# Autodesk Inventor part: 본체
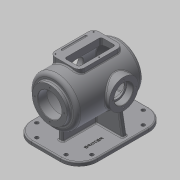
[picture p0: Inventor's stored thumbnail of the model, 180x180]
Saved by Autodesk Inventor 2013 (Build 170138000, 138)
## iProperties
Created: 2016-02
Part Number: 본체
Material: 일반
Document SubType Name: Modeling
Designer: mduedu
Density: 2.71 g/cm^3
Author: mduedu
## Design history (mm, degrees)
sketch "스케치2"
  geometry: L1 (0, 100)-(0, -100); L2 (65, -75.993)-(65, 100); L3 (65, 100)-(0, 100); A1 r 100 centre (0, 0) between (0, -100) and (65, -75.993); 2 further points
  constraints: 6 end point, 2 midpoint, 2 point on circle, 1 centre point, 1 coincident, 1 horizontal, 1 parallel, 1 vertical
  dimensions: "d3" = 200 distance of L1.start L1.end; "d5" = 130 diameter of L2 L1; "d6" = 100 radius of A1
revolve "회전1" sketch "스케치2" stored, may be unused: angle "d7" = 90 deg
sketch "스케치3"
  geometry: C1 r 47.5 at (0, 0); 1 further point
  constraints: 1 centre point, 1 coincident
  dimensions: "d8" = 95 diameter of C1
extrude "돌출2" join sketch "스케치3" distance "d10" = 10; taper "d11" = 0 deg
sketch "스케치5"
  geometry: L1 (47.5, 110)-(47.5, 100) reference; L2 (47.5, 100)-(65, 100) reference; L3 (65, 100)-(65, -75.993) reference; L4 (-65, -75.993)-(-65, 100) reference; L5 (-65, 100)-(-47.5, 100) reference; L6 (-47.5, 100)-(-47.5, 110) reference; L7 (-47.5, 110)-(47.5, 110) reference; L8 (55, 85)-(55, -71.239); L9 (0, 85)-(55, 85); L10 (0, 85)-(0, -90); A1 r 100 centre (0, 0) between (0, -100) and (65, -75.993) reference; A2 r 100 centre (0, 0) between (-65, -75.993) and (0, -100) reference; A3 r 90 centre (0, 0) between (0, -90) and (55, -71.239); 1 further point
  constraints: 6 end point, 2 point on circle, 1 centre point, 1 parallel, 1 perpendicular, 1 point on line, 1 vertical
  dimensions: "d13" = 10 distance between parallel lines of L3 L8; "d14" = 10 radial gap between concentric circles of A3 A1; "d15" = 15 distance between parallel lines of L9 L2
revolve "회전2" sketch "스케치5" stored, may be unused: angle "d16" = 90 deg
hole "구멍1" diameter "d19" = 65; stored, may be unused: countersink angle "d23" = 90 deg, drill point angle "d25" = 118 deg; dims "d17" = 10, "d18" = 10, "d20" = 6, "d21" = 4, "d22" = 2, "d24" = 8
node "작업 평면1"
sketch "스케치6"
  geometry: L1 (47.5, 110)-(-47.5, 110) reference; C1 r 40 at (0, -17); 1 further point
  constraints: 1 centre point, 1 vertical alignment
  dimensions: "d27" = 80 diameter of C1; "d29" = 127 distance from line of C1.centre L1
extrude "돌출3" join sketch "스케치6" stored distance "d30" = 10; taper "d31" = 0 deg
hole "구멍2" diameter "d34" = 42; stored, may be unused: countersink angle "d38" = 90 deg, drill point angle "d40" = 118 deg; dims "d32" = 10, "d33" = 10, "d35" = 6, "d36" = 52, "d37" = 18, "d39" = 8
sketch "스케치7" dims "d41" = 65
  geometry: C1 r 40 at (0, 0) reference; 3 further points
  constraints: 2 vertical alignment, 1 coincident, 2 other
hole "구멍3" sketch "스케치7" at (0, 32.5) diameter "d43" = 3.242; stored, may be unused: countersink angle "d47" = 90 deg, drill point angle "d49" = 118 deg; dims "d44" = 11, "d45" = 13, "d46" = 18, "d48" = 13
sketch "스케치8" dims "d53" = 80
  geometry: 3 further points
  constraints: 2 vertical alignment, 1 coincident, 2 other
hole "구멍4" sketch "스케치8" at (0, 40) diameter "d56" = 3.242; stored, may be unused: countersink angle "d60" = 90 deg, drill point angle "d62" = 118 deg; dims "d57" = 11, "d58" = 13, "d59" = 18, "d61" = 13
fillet "모깎기1" dims "d66" = 10
fillet "모깎기2" dims "d67" = 3
fillet "모깎기3" dims "d68" = 0.3
chamfer "모따기1" distance "d69" = 1; stored, may be unused: second distance "d70" = 2, angle "d71" = 45 deg
node "작업 평면5"
sketch "스케치23"
  geometry: L1 (6, 80)-(-6, 80); L2 (-6, 80)-(-6, -60); L3 (-6, -60)-(6, -60); L4 (6, -60)-(6, 80); L5 (-55, 100)-(55, 100) reference; 2 further points
  constraints: 8 end point, 2 parallel, 1 horizontal, 1 midpoint, 1 perpendicular, 1 vertical alignment
  dimensions: "d177" = 12 distance of L1.start L1.end; "d179" = 140 distance of L3.end L1.start; "d180" = 20 distance between parallel lines of L1 L5
extrude "돌출14" join sketch "스케치23" stored distance "d181" = 10; taper "d182" = 0 deg
node "작업 평면6"
sketch "스케치15"
  geometry: L1 (-30, 60)-(50, 60); L2 (50, 60)-(50, -60); L3 (50, -60)-(-30, -60); L4 (-30, -60)-(-30, 60); 3 further points
  constraints: 8 end point, 2 parallel, 1 horizontal, 1 horizontal alignment, 1 midpoint, 1 perpendicular, 1 vertical alignment
  dimensions: "d110" = 80 distance of L2.end L3.end; "d112" = 60 distance from line of L3 point (10, 0); "d113" = 120 distance of L1.end L2.end; "d149" = 30 distance from line of L4 point (0, 0)
extrude "돌출8" join sketch "스케치15" stored distance "d114" = 10; taper "d115" = 0 deg
fillet "모깎기7" dims "d116" = 15
sketch "스케치16"
  geometry: L1 (-30, -45)-(-30, 45) reference; L2 (-15, 60)-(35, 60) reference; L3 (35, -60)-(-15, -60) reference; L4 (-20, -45)-(-20, 45); L5 (-15, 50)-(15, 50); L6 (20, 45)-(20, -45); L7 (15, -50)-(-15, -50); L8 (50, 45)-(50, -45) reference; A1 r 15 centre (-15, -45) between (-30, -45) and (-15, -60) reference; A2 r 15 centre (-15, 45) between (-15, 60) and (-30, 45) reference; A3 r 5 centre (-15, -45) between (-20, -45) and (-15, -50); A4 r 5 centre (-15, 45) between (-15, 50) and (-20, 45); A5 r 5 centre (15, 45) between (20, 45) and (15, 50); A6 r 5 centre (15, -45) between (15, -50) and (20, -45); A7 r 15 centre (35, 45) between (50, 45) and (35, 60) reference; A8 r 15 centre (35, -45) between (35, -60) and (50, -45) reference
  constraints: 8 end point, 8 point on circle, 4 centre point, 2 equal radius, 3 other
  dimensions: "d137" = 10 distance between parallel lines of L4 L1; "d150" = 40 distance between parallel lines of L6 L4; "d151" = 100 distance between parallel lines of L7 L5
extrude "돌출9" cut sketch "스케치16" stored distance "d118" = 10; taper "d119" = 0 deg
fillet "모깎기8" dims "d120" = 3
sketch "스케치17"
  geometry: L1 (-30, -45)-(-30, 45) reference; L2 (-20, 45)-(-20, -45) reference; L3 (-15, -50)-(15, -50) reference; L4 (20, -45)-(20, 45) reference; L5 (15, 50)-(-15, 50) reference; L6 (-15, 60)-(35, 60) reference; L7 (35, -60)-(-15, -60) reference; L8 (15, 55)-(-15, 55); L9 (-25, 45)-(-25, -45); L10 (-15, -55)-(15, -55); L11 (25, -45)-(25, 45); L12 (50, 45)-(50, -45) reference; L13 (35, 55)-(-15, 55); L14 (-25, 45)-(-25, -45); L15 (-15, -55)-(35, -55); L16 (45, -45)-(45, 45); A1 r 5 centre (-15, 45) between (-15, 50) and (-20, 45) reference; A2 r 5 centre (-15, -45) between (-20, -45) and (-15, -50) reference; A3 r 5 centre (15, -45) between (15, -50) and (20, -45) reference; A4 r 5 centre (15, 45) between (20, 45) and (15, 50) reference; A5 r 15 centre (-15, 45) between (-15, 60) and (-30, 45) reference; A6 r 15 centre (-15, -45) between (-30, -45) and (-15, -60) reference; A7 r 10 centre (-15, 45) between (-15, 55) and (-25, 45); A8 r 10 centre (-15, -45) between (-25, -45) and (-15, -55); A9 r 10 centre (15, -45) between (15, -55) and (25, -45); A10 r 10 centre (15, 45) between (25, 45) and (15, 55); A11 r 15 centre (35, 45) between (50, 45) and (35, 60) reference; A12 r 15 centre (35, -45) between (35, -60) and (50, -45) reference; A13 r 10 centre (-15, 45) between (-15, 55) and (-25, 45); A14 r 10 centre (-15, -45) between (-25, -45) and (-15, -55); A15 r 10 centre (35, -45) between (35, -55) and (45, -45); A16 r 10 centre (35, 45) between (45, 45) and (35, 55); 6 further points
  constraints: 18 point on circle, 16 end point, 8 centre point, 4 midpoint, 4 tangent, 11 other
  dimensions: "d138" = 5 distance between parallel lines of L8 L6; "d157" = 5 distance between parallel lines of L12 L16
hole "구멍5" sketch "스케치17" at (-25, 0), (42.071, 52.071), (42.071, -52.071) diameter "d122" = 3.242; stored, may be unused: countersink angle "d126" = 90 deg, drill point angle "d128" = 118 deg; dims "d123" = 9, "d124" = 13, "d125" = 18, "d127" = 11
sketch "스케치19"
  geometry: L1 (-50, 70)-(-35, 70) reference; L2 (-50, 42.603)-(-50, 70) reference; C1 r 2.5 at (-43, 70); 1 further point
  constraints: 1 centre point, 1 point on line
  dimensions: "d152" = 5 diameter of C1; "d153" = 7 distance from line of C1.centre L2
extrude "돌출11" cut sketch "스케치19" stored distance "d154" = 70; taper "d155" = 0 deg
fillet "모깎기11" dims "d156" = 2.5
sketch "스케치20"
  geometry: L1 (-90, 120)-(90, 120); L2 (90, 120)-(90, -120); L3 (90, -120)-(-90, -120); L4 (-90, -120)-(-90, 120); 3 further points
  constraints: 8 end point, 2 parallel, 2 vertical alignment, 1 coincident, 1 horizontal, 1 midpoint, 1 perpendicular
  dimensions: "d162" = 180 distance of L1.start L1.end; "d164" = 240 distance of L1.end L2.end; "d165" = 120 distance from line of L1 point (0, 0)
extrude "돌출12" join sketch "스케치20" distance "d166" = 10; taper "d167" = 0 deg
fillet "모깎기12" dims "d168" = 50
node "작업 평면8"
  node "작업축1"
sketch "스케치24"
  geometry: L1 (128, 34.121)-(127.026, 32.5) reference; L2 (127.026, 32.5)-(128, 30.879) reference; L3 (128, 30.879)-(141, 30.879) reference; L4 (141, 30.879)-(141, 27) reference; L5 (141, 27)-(140, 26) reference; L6 (140, 26)-(123.3, 26) reference; L7 (123, 25.7)-(123, 21) reference; L8 (123, 21)-(116.833, 21) reference; L9 (86, 51.235)-(86, 70) reference; L10 (86, 70)-(106.5, 70) reference; L11 (111.5, 70)-(116, 70) reference; L12 (116, 70)-(116, 42.603) reference; L13 (118.678, 40)-(141, 40) reference; L14 (141, 40)-(141, 34.121) reference; L15 (141, 34.121)-(128, 34.121) reference; L16 (4, -34.121)-(4.974, -32.5) reference; L17 (4.974, -32.5)-(4, -30.879) reference; L18 (4, -30.879)-(-9, -30.879) reference; L19 (-9, -30.879)-(-9, -27) reference; L20 (-9, -27)-(-8, -26) reference; L21 (-8, -26)-(8.7, -26) reference; L22 (9, -25.7)-(9, -21) reference; L23 (9, -21)-(15.167, -21) reference; L24 (116.833, -21)-(123, -21) reference; L25 (123, -21)-(123, -25.7) reference; L26 (123.3, -26)-(140, -26) reference; L27 (140, -26)-(141, -27) reference; L28 (141, -27)-(141, -30.879) reference; L29 (141, -30.879)-(128, -30.879) reference; L30 (128, -30.879)-(127.026, -32.5) reference; L31 (127.026, -32.5)-(128, -34.121) reference; L32 (128, -34.121)-(141, -34.121) reference; L33 (141, -34.121)-(141, -40) reference; L34 (141, -40)-(118.678, -40) reference; L35 (72, -64.722)-(72, -100) reference; L36 (72, -100)-(156, -100) reference; L37 (156, -100)-(156, -110) reference; L38 (156, -110)-(-24, -110) reference; L39 (-24, -110)-(-24, -100) reference; L40 (-24, -100)-(60, -100) reference; L41 (60, -100)-(60, -64.722) reference; L42 (13.322, -40)-(-9, -40) reference; L43 (-9, -40)-(-9, -34.121) reference; L44 (-9, -34.121)-(4, -34.121) reference; L45 (4.974, 32.5)-(4, 34.121) reference; L46 (4, 34.121)-(-9, 34.121) reference; L47 (-9, 34.121)-(-9, 40) reference; L48 (-9, 40)-(13.322, 40) reference; L49 (36, 59.456)-(36, 70) reference; L50 (36, 70)-(46, 70) reference; L51 (46, 70)-(46, 51.235) reference; L52 (15.167, 21)-(9, 21) reference; L53 (9, 21)-(9, 25.7) reference; L54 (8.7, 26)-(-8, 26) reference; L55 (-8, 26)-(-9, 27) reference; L56 (-9, 27)-(-9, 30.879) reference; L57 (-9, 30.879)-(4, 30.879) reference; L58 (4, 30.879)-(4.974, 32.5) reference; L59 (-1, -40)-(-11.58, -100); A1 r 0.3 centre (123.3, 25.7) between (123.3, 26) and (123, 25.7) reference; A2 r 55 centre (66, 0) between (116.833, 21) and (86, 51.235) reference; A3 r 2.5 centre (109, 70) between (106.5, 70) and (111.5, 70) reference; A4 r 3 centre (119, 42.603) between (116, 42.603) and (116.516, 40.92) reference; A5 r 0.3 centre (8.7, -25.7) between (8.7, -26) and (9, -25.7) reference; A6 r 55 centre (66, 0) between (15.167, -21) and (116.833, -21) reference; A7 r 0.3 centre (123.3, -25.7) between (123, -25.7) and (123.3, -26) reference; A8 r 65 centre (66, 0) between (72, -64.722) and (116.354, -41.103) reference; A9 r 65 centre (66, 0) between (15.646, -41.103) and (60, -64.722) reference; A10 r 65 centre (66, 0) between (34.456, 56.833) and (15.646, 41.103) reference; A11 r 3 centre (33, 59.456) between (34.456, 56.833) and (36, 59.456) reference; A12 r 55 centre (66, 0) between (46, 51.235) and (15.167, 21) reference; A13 r 0.3 centre (8.7, 25.7) between (9, 25.7) and (8.7, 26) reference; 1 further point
  constraints: 2 end point, 2 point on line, 4 other
  dimensions: "d184" = 8 distance of L59.start L42.end; "d185" = 100 deg angle of L59 L40
feature "리브2" sketch "스케치24" dims "d186" = 1, "d187" = 12, "d188" = 0, "d189" = 0, "d190" = 1, "d191" = 1
fillet "모깎기15" dims "d192" = 3
fillet "모깎기16" dims "d193" = 3
sketch "스케치25"
  geometry: L1 (90, -70)-(90, 70) reference; L2 (40, 120)-(-40, 120) reference; L3 (-90, 70)-(-90, -70) reference; L4 (-40, -120)-(40, -120) reference; L5 (-74.004, 8)-(-9, 8) reference; L6 (-80.097, 20)-(-80.097, 14) reference; L7 (-9, 26)-(-74.004, 26) reference; L8 (-9, 57)-(-9, 26) reference; L9 (3, 63)-(-3, 63) reference; L10 (9, 26)-(9, 57) reference; L11 (74.004, 26)-(9, 26) reference; L12 (80.097, 14)-(80.097, 20) reference; L13 (9, 8)-(74.004, 8) reference; L14 (9, -77)-(9, 8) reference; L15 (-3, -83)-(3, -83) reference; L16 (-9, 8)-(-9, -77) reference; L17 (-40, 105)-(40, 105); L18 (75, 70)-(75, -70); L19 (40, -105)-(-40, -105); L20 (-75, -70)-(-75, 70); C1 r 5 at (-75, 70); C2 r 5 at (-40, 105); C3 r 5 at (40, 105); C4 r 5 at (75, 70); C5 r 5 at (75, -70); C6 r 5 at (40, -105); C7 r 5 at (-40, -105); C8 r 5 at (-75, -70); A1 r 50 centre (40, 70) between (90, 70) and (40, 120) reference; A2 r 50 centre (-40, 70) between (-40, 120) and (-90, 70) reference; A3 r 50 centre (-40, -70) between (-90, -70) and (-40, -120) reference; A4 r 50 centre (40, -70) between (40, -120) and (90, -70) reference; A5 r 6 centre (-3, 57) between (-3, 63) and (-9, 57) reference; A6 r 6 centre (3, 57) between (9, 57) and (3, 63) reference; A7 r 6 centre (3, -77) between (3, -83) and (9, -77) reference; A8 r 6 centre (-3, -77) between (-9, -77) and (-3, -83) reference; A9 r 35 centre (40, 70) between (75, 70) and (40, 105); A10 r 35 centre (40, -70) between (40, -105) and (75, -70); A11 r 35 centre (-40, -70) between (-75, -70) and (-40, -105); A12 r 35 centre (-40, 70) between (-40, 105) and (-75, 70); 5 further points; 4 other entities
  constraints: 12 centre point, 8 coincident, 8 end point, 8 point on circle, 7 equal radius, 11 other
  dimensions: "d194" = 15 distance between parallel lines of L17 L2; "d195" = 10 diameter of C1
extrude "돌출15" cut sketch "스케치25" stored distance "d197" = 10; taper "d198" = 0 deg
fillet "모깎기14" dims "d170" = 3
sketch "스케치22"
  geometry: L1 (90, -70)-(90, 70) reference; 2 further points
  constraints: 1 other
  dimensions: "d174" = 40 distance from line of L1 point (50, -40); "d199" = 40 vertical distance of point (50, -40) point (0, 0)
feature "엠보싱2" sketch "스케치22" dims "d13" = 10, "d175" = 0.5, "d176" = 0
node "솔리드2"
pattern_circular "원형 패턴1" dims angle "d51" = 360 deg
mirror "대칭1"
pattern_circular "원형 패턴2" dims angle "d64" = 360 deg
mirror "대칭3"
node "투영된 루프2"
node "절단 모서리 투영1"
node "절단 모서리 투영2"
node "절단 모서리 투영3"
node "절단 모서리 투영4"
other parameters: "d26" = 75, "d183" = 0
